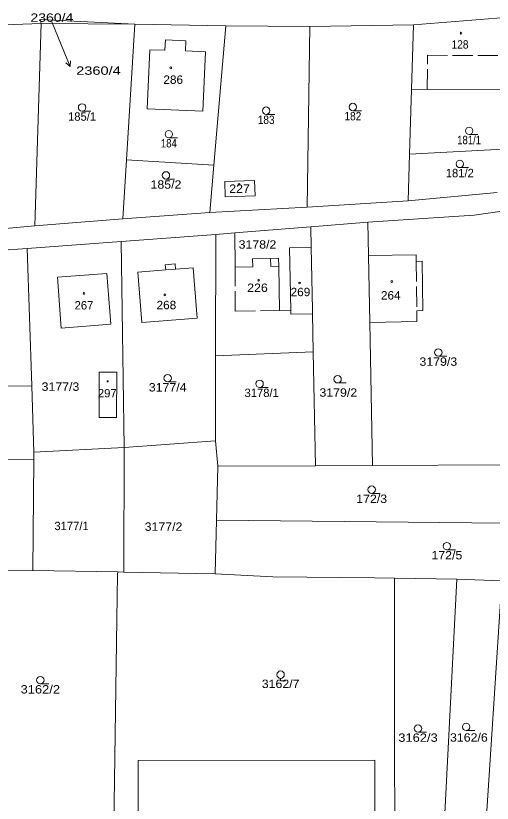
# Model space of a CAD drawing. Extents: x -590528 to -586543, y -1119609 to -1116685.
# Drawn here: x -588794.5 to -588698, y -1118281.3 to -1118121.8 of the extents above; entities that cross this region are included whole.
import ezdxf
from ezdxf.enums import TextEntityAlignment as Align

# ---------------------------------------------------------------- set-up
doc = ezdxf.new("R2010")
doc.units = 0
doc.header["$LTSCALE"] = 0.68
doc.linetypes.add('LONG_DASHED', pattern=[7.5, 6, -1.5])
for name, color, linetype, lineweight in [('1', 7, 'Continuous', 13), ('2', 7, 'LONG_DASHED', 13), ('3', 7, 'Continuous', 13), ('6', 7, 'Continuous', 13)]:
    doc.layers.add(name, color=color, linetype=linetype, lineweight=lineweight)

msp = doc.modelspace()

# ---------------------------------------------------------------- linework, layer by layer
at = {"layer": '1'}
for p, q in [((-588713.9, -1118123.63), (-588695.33, -1118122.16)), ((-588770.39, -1118123.5), (-588789.39, -1118123.38)), ((-588770.39, -1118123.5), (-588772.06, -1118150.95)), ((-588770.39, -1118123.5), (-588751.95, -1118123.86)), ((-588751.95, -1118123.86), (-588754.39, -1118152.03)), ((-588751.95, -1118123.86), (-588734.95, -1118123.97)), ((-588735.43, -1118160.56), (-588734.95, -1118123.97)), ((-588713.9, -1118123.63), (-588734.95, -1118123.97)), ((-588764.18, -1118126.67), (-588764.3, -1118128.76)), ((-588714.3, -1118136.69), (-588714.7, -1118149.82)), ((-588711.12, -1118136.71), (-588695.41, -1118136.78)), ((-588714.7, -1118149.82), (-588714.99, -1118159.28)), ((-588714.7, -1118149.82), (-588695.82, -1118148.8)), ((-588772.06, -1118150.95), (-588772.79, -1118162.92)), ((-588772.06, -1118150.95), (-588754.39, -1118152.03)), ((-588754.39, -1118152.03), (-588755.22, -1118161.64)), ((-588745.97, -1118158.28), (-588746.13, -1118155.16)), ((-588696.93, -1118157.62), (-588714.99, -1118159.28)), ((-588752.06, -1118158.48), (-588745.97, -1118158.28)), ((-588714.99, -1118159.28), (-588735.43, -1118160.56)), ((-588755.22, -1118161.64), (-588735.43, -1118160.56)), ((-588772.79, -1118162.92), (-588790.67, -1118164.38)), ((-588772.79, -1118162.92), (-588755.22, -1118161.64)), ((-588701.64, -1118162.19), (-588723.14, -1118163.64)), ((-588790.67, -1118164.38), (-588811.54, -1118166.12)), ((-588723.14, -1118163.64), (-588734.73, -1118164.57)), ((-588754.02, -1118190.69), (-588753.98, -1118166.11)), ((-588734.73, -1118164.57), (-588750.12, -1118165.8)), ((-588750.08, -1118172.76), (-588750.12, -1118165.8)), ((-588734.73, -1118164.57), (-588734.65, -1118168.7)), ((-588773.14, -1118167.52), (-588792.21, -1118168.92)), ((-588773.14, -1118167.52), (-588772.53, -1118209.28)), ((-588739.04, -1118168.79), (-588734.65, -1118168.7)), ((-588734.65, -1118168.7), (-588734.39, -1118181.35)), ((-588764.22, -1118172.24), (-588762.22, -1118172.08)), ((-588764.13, -1118173.29), (-588764.22, -1118172.24)), ((-588762.22, -1118172.08), (-588762.14, -1118173.13)), ((-588741.23, -1118172.53), (-588741.05, -1118181.48)), ((-588764.13, -1118173.29), (-588769.81, -1118173.74)), ((-588769, -1118183.91), (-588769.81, -1118173.74)), ((-588762.14, -1118173.13), (-588758.55, -1118172.84)), ((-588741.05, -1118181.48), (-588738.79, -1118181.44)), ((-588734.37, -1118182.2), (-588734.22, -1118189.89)), ((-588722.23, -1118212.91), (-588722.77, -1118183.91)), ((-588754.02, -1118190.69), (-588734.22, -1118189.89)), ((-588734.22, -1118189.89), (-588733.76, -1118212.97)), ((-588754.05, -1118207.93), (-588754.02, -1118190.69)), ((-588791.29, -1118196.8), (-588809.23, -1118196.92)), ((-588791.29, -1118196.8), (-588790.85, -1118210.24)), ((-588772.53, -1118209.28), (-588754.05, -1118207.93)), ((-588754.05, -1118207.93), (-588753.56, -1118213.07)), ((-588790.85, -1118210.24), (-588772.53, -1118209.28)), ((-588772.53, -1118209.28), (-588772.6, -1118234.5)), ((-588790.86, -1118211.7), (-588809.06, -1118211.89)), ((-588753.83, -1118223.97), (-588695.62, -1118224.58)), ((-588773.87, -1118234.93), (-588773.86, -1118234.48)), ((-588772.6, -1118234.5), (-588754.1, -1118234.86)), ((-588754.1, -1118234.86), (-588742.44, -1118235.45)), ((-588717.73, -1118235.71), (-588717.73, -1118271.19)), ((-588705.15, -1118235.97), (-588696.04, -1118236.25)), ((-588696.04, -1118236.25), (-588704.69, -1118371.28)), ((-588717.61, -1118328.06), (-588717.73, -1118271.19)), ((-588769.59, -1118340.66), (-588769.73, -1118272.69))]:
    msp.add_line(p, q, dxfattribs=at)
for points in [[(-588789.39, -1118123.38), (-588789.56, -1118122.53), (-588770.39, -1118123.5)], [(-588810.07, -1118124.07), (-588789.39, -1118123.38), (-588790.67, -1118164.38)], [(-588713.9, -1118123.63), (-588714.3, -1118136.69), (-588711.12, -1118136.71)], [(-588760.12, -1118128.89), (-588760.03, -1118126.85), (-588764.18, -1118126.67)], [(-588764.3, -1118128.76), (-588767.38, -1118128.66), (-588767.92, -1118140.65)], [(-588767.92, -1118140.65), (-588756.62, -1118141.14), (-588756.05, -1118129.1), (-588760.12, -1118128.89)], [(-588752.06, -1118158.48), (-588752.18, -1118155.4), (-588746.13, -1118155.16)], [(-588701.64, -1118162.19), (-588695.94, -1118161.41), (-588689.45, -1118160.52)], [(-588722.77, -1118183.91), (-588723.02, -1118170.39), (-588723.14, -1118163.64)], [(-588750.12, -1118165.8), (-588753.98, -1118166.11), (-588773.14, -1118167.52)], [(-588809.52, -1118170.19), (-588792.21, -1118168.92), (-588791.29, -1118196.8)], [(-588738.77, -1118182.28), (-588738.79, -1118181.44), (-588739.04, -1118168.79)], [(-588742.86, -1118170.96), (-588741.26, -1118170.93), (-588741.23, -1118172.53)], [(-588723.02, -1118170.39), (-588713.4, -1118170.26), (-588713.38, -1118171.56), (-588712.13, -1118171.54), (-588712, -1118181.54), (-588713.25, -1118181.56), (-588713.22, -1118183.74), (-588722.77, -1118183.91)], [(-588750.08, -1118172.76), (-588746.47, -1118172.69), (-588746.51, -1118171.04), (-588742.86, -1118170.96)], [(-588758.55, -1118172.84), (-588757.73, -1118183.06), (-588769, -1118183.91)], [(-588734.39, -1118181.35), (-588734.37, -1118182.2), (-588738.77, -1118182.28)], [(-588790.85, -1118210.24), (-588790.86, -1118211.7), (-588791.09, -1118234.19)], [(-588753.56, -1118213.07), (-588753.83, -1118223.97), (-588754.1, -1118234.86)], [(-588695.65, -1118212.77), (-588722.23, -1118212.91), (-588733.76, -1118212.97), (-588753.56, -1118213.07)], [(-588808.81, -1118234.37), (-588805.82, -1118234.34), (-588791.09, -1118234.19), (-588773.86, -1118234.48), (-588772.6, -1118234.5)], [(-588774.74, -1118290.68), (-588774.01, -1118244.1), (-588773.87, -1118234.93)], [(-588742.44, -1118235.45), (-588721.81, -1118235.67), (-588717.73, -1118235.71)], [(-588717.73, -1118235.71), (-588705.15, -1118235.97), (-588711.91, -1118367.77)], [(-588769.73, -1118272.69), (-588721.73, -1118272.59), (-588721.54, -1118363.15)]]:
    msp.add_lwpolyline(points, dxfattribs=at)
for points in [[(-588786.08, -1118174.78), (-588776.03, -1118173.98), (-588775.22, -1118184.3), (-588785.29, -1118185.09)], [(-588777.62, -1118194.03), (-588774.06, -1118194.02), (-588774.09, -1118203.22), (-588777.62, -1118203.22)]]:
    msp.add_lwpolyline(points, close=True, dxfattribs=at)
at = {"layer": '2'}
for p, q in [((-588711.12, -1118136.71), (-588711.08, -1118129.79)), ((-588711.08, -1118129.79), (-588695.37, -1118129.88)), ((-588713.38, -1118171.56), (-588713.25, -1118181.56)), ((-588764.13, -1118173.29), (-588762.14, -1118173.13)), ((-588750.03, -1118181.66), (-588750.08, -1118172.76)), ((-588750.03, -1118181.66), (-588741.05, -1118181.48))]:
    msp.add_line(p, q, dxfattribs=at)
msp.add_lwpolyline([(-588742.86, -1118170.96), (-588742.83, -1118172.57), (-588741.23, -1118172.53)], dxfattribs=at)
at = {"layer": '3'}
for p in [(-588787.2, -1118123.01), (-588783.504, -1118132.047)]:
    msp.add_line(p, (-588784.64, -1118129.27), dxfattribs=at)
msp.add_lwpolyline([(-588783.421, -1118130.933), (-588783.504, -1118132.047), (-588784.346, -1118131.31)], dxfattribs=at)
at = {"layer": '6'}
for p, q in [((-588781.08, -1118141.11), (-588779.33, -1118141.11)), ((-588743.77, -1118141.77), (-588742.02, -1118141.77)), ((-588726.2, -1118141.03), (-588724.45, -1118141.03)), ((-588763.49, -1118146.52), (-588761.74, -1118146.52)), ((-588702.64, -1118145.86), (-588700.89, -1118145.86)), ((-588704.53, -1118152.56), (-588702.78, -1118152.56)), ((-588764.08, -1118154.88), (-588762.33, -1118154.88)), ((-588708.88, -1118190.76), (-588707.13, -1118190.76)), ((-588763.73, -1118195.97), (-588761.98, -1118195.97)), ((-588729.29, -1118196.19), (-588727.54, -1118196.19)), ((-588745.1, -1118197.1), (-588743.35, -1118197.1)), ((-588722.39, -1118218.56), (-588720.64, -1118218.56)), ((-588707.15, -1118229.99), (-588705.4, -1118229.99)), ((-588789.54, -1118257.16), (-588787.79, -1118257.16)), ((-588703.25, -1118266.63), (-588701.5, -1118266.63)), ((-588713, -1118266.95), (-588711.25, -1118266.95))]:
    msp.add_line(p, q, dxfattribs=at)
msp.add_lwpolyline([(-588740.84, -1118256.05), (-588740.84, -1118256.55), (-588739.84, -1118256.55)], dxfattribs=at)
for centre, radius in [((-588704.2902, -1118125.3104), 0.175), ((-588763.1002, -1118132.3404), 0.175), ((-588781.08, -1118140.36), 0.75), ((-588743.77, -1118141.02), 0.75), ((-588726.2, -1118140.28), 0.75), ((-588763.49, -1118145.77), 0.75), ((-588702.64, -1118145.11), 0.75), ((-588704.53, -1118151.81), 0.75), ((-588764.08, -1118154.13), 0.75), ((-588749.2502, -1118155.9404), 0.175), ((-588745.3002, -1118175.3904), 0.175), ((-588718.3002, -1118175.6504), 0.175), ((-588737.0002, -1118175.9304), 0.175), ((-588780.6902, -1118178.0504), 0.175), ((-588764.2902, -1118178.3304), 0.175), ((-588708.88, -1118190.01), 0.75), ((-588763.73, -1118195.22), 0.75), ((-588729.29, -1118195.44), 0.75), ((-588775.9001, -1118195.8502), 0.1172), ((-588745.1, -1118196.35), 0.75), ((-588722.39, -1118217.81), 0.75), ((-588707.15, -1118229.24), 0.75), ((-588740.84, -1118255.3), 0.75), ((-588789.54, -1118256.41), 0.75), ((-588713, -1118266.2), 0.75), ((-588703.25, -1118265.88), 0.75)]:
    msp.add_circle(centre, radius, dxfattribs=at)

# ---------------------------------------------------------------- texts
at = {"layer": '3'}
for s, width, p in [('2360/4', 1.25, (-588787.2015, -1118123.01)), ('128', 0.9, (-588704.48, -1118128.45)), ('286', 1.05, (-588762.6105, -1118135.59)), ('183', 0.9, (-588743.7705, -1118143.72)), ('182', 0.9, (-588726.2005, -1118142.98)), ('184', 0.85, (-588763.4905, -1118148.47)), ('181/1', 0.85, (-588702.6405, -1118147.81)), ('185/2', 1.1, (-588764.08, -1118156.83)), ('227', 1.1, (-588749.17, -1118157.67)), ('3178/2', 1.1, (-588745.5305, -1118168.98)), ('226', 1.1, (-588745.53, -1118177.75)), ('269', 1.05, (-588736.8205, -1118178.61)), ('264', 1.05, (-588718.5205, -1118179.28)), ('268', 1.05, (-588763.99, -1118181.25)), ('3179/3', 1.1, (-588708.88, -1118192.71)), ('3177/3', 1.1, (-588785.46, -1118197.78)), ('3177/4', 1.1, (-588763.73, -1118197.92)), ('3179/2', 1.1, (-588729.1505, -1118198.98)), ('172/3', 1.1, (-588722.3905, -1118220.51)), ('3177/2', 1.1, (-588764.5705, -1118226.15)), ('172/5', 1.1, (-588707.151, -1118231.94)), ('3162/7', 1.1, (-588740.8405, -1118258)), ('3162/2', 1.15, (-588789.5405, -1118259.11)), ('3162/3', 1.15, (-588713, -1118268.9)), ('3162/6', 1.1, (-588702.69, -1118268.87))]:
    msp.add_text(s, height=1.7, dxfattribs=dict(at, width=width)).set_placement(p, align=Align.CENTER)
at = {"layer": '3', "width": 1.3}
msp.add_text('2360/4', height=1.7, dxfattribs=at).set_placement((-588782.273, -1118133.75))
at = {"layer": '3'}
for s, p in [('185/1', (-588781.0805, -1118143.06)), ('181/2', (-588704.531, -1118154.51)), ('267', (-588780.6905, -1118181.3)), ('297', (-588775.9715, -1118199.11)), ('3178/1', (-588744.6805, -1118199.04)), ('3177/1', (-588783.21, -1118226.01))]:
    msp.add_text(s, height=1.7, dxfattribs=at).set_placement(p, align=Align.CENTER)

doc.saveas('drawing.dxf')
